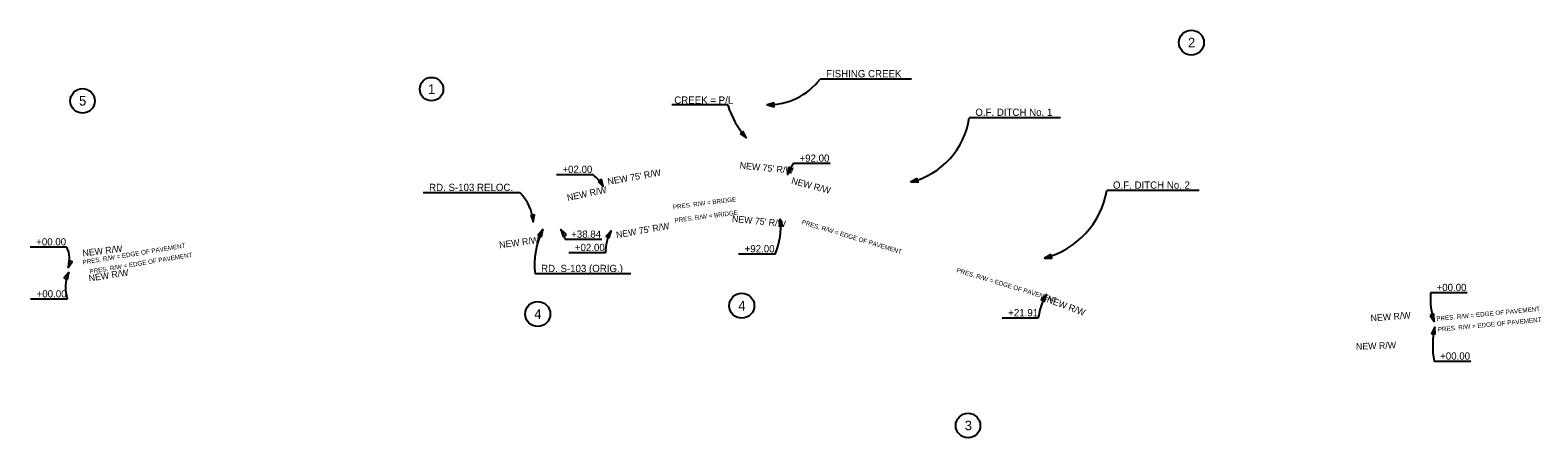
# Model space of a CAD drawing. Extents: x 1959715 to 1970746, y 1118442 to 1119852.
import ezdxf

# ---------------------------------------------------------------- set-up
doc = ezdxf.new("R2010")
doc.units = 0
for name, color, linetype in [('RD_EX_DV_TX_Prop', 7, 'Continuous'), ('RD_EX_RW_TX', 7, 'Continuous'), ('RD_PD_RW_TX', 7, 'Continuous'), ('RD_TX_RoadID', 7, 'Continuous')]:
    doc.layers.add(name, color=color, linetype=linetype)

msp = doc.modelspace()

# ---------------------------------------------------------------- linework, layer by layer
at = {"layer": 'RD_EX_DV_TX_Prop'}
msp.add_line((1968063.1, 1119604.2), (1967877.9, 1119604.2), dxfattribs=at)
msp.add_lwpolyline([(1968104.6, 1119508.1), (1968124.6, 1119494.8), (1968113.9, 1119516.3)], close=True, dxfattribs=at)
for centre, radius in [((1969598.8, 1119810.6), 41.4), ((1967082, 1119656.5), 38.9), ((1965926, 1119617.5), 40.6), ((1968109.5, 1118938.6), 41.6), ((1967433.8, 1118911), 41.6), ((1968858.9, 1118541.2), 40.7)]:
    msp.add_circle(centre, radius, dxfattribs=at)
msp.add_arc((1968348.3, 1119692.7), 298.6, 197.24, 221.4995, dxfattribs=at)
at = {"layer": 'RD_PD_RW_TX'}
for p, q in [((1967616.9, 1119372.6), (1967495.4, 1119372.6)), ((1968402.2, 1119409.7), (1968280.7, 1119409.7)), ((1965874, 1119132.3), (1965752.6, 1119132.3)), ((1967645.9, 1119157.7), (1967524.4, 1119157.7)), ((1967658.1, 1119113.7), (1967536.7, 1119113.7)), ((1968220.5, 1119109.5), (1968099.1, 1119109.5)), ((1970512.1, 1118981.1), (1970390.7, 1118981.1)), ((1965875.6, 1118959.9), (1965754.1, 1118959.9)), ((1969091.4, 1118897.3), (1968972, 1118897.3)), ((1970524.1, 1118753.8), (1970402.6, 1118753.8))]:
    msp.add_line(p, q, dxfattribs=at)
for points in [[(1968263.8, 1119397.6), (1968260.6, 1119373.8), (1968275.2, 1119392.9)], [(1967633.7, 1119350.8), (1967650.7, 1119333.9), (1967644.4, 1119357)], [(1968246, 1119203.4), (1968237, 1119225.7), (1968233.6, 1119201.9)], [(1967528.5, 1119174.9), (1967510.5, 1119190.7), (1967518.2, 1119168)], [(1967670.6, 1119163), (1967677, 1119186.2), (1967659.9, 1119169.3)], [(1965880.4, 1119088.6), (1965878.5, 1119064.7), (1965892.1, 1119084.4)], [(1965876.8, 1119025.3), (1965881.2, 1119048.9), (1965865.5, 1119030.7)], [(1969112.1, 1118952.5), (1969118.9, 1118975.5), (1969101.5, 1118959)], [(1970389.6, 1118906.2), (1970402.8, 1118886.1), (1970401.4, 1118910.1)], [(1970405.7, 1118843.7), (1970404.6, 1118867.7), (1970393.5, 1118846.4)]]:
    msp.add_lwpolyline(points, close=True, dxfattribs=at)
for centre, radius, start, end in [((1967533, 1119265.2), 136.2, 30.2443, 52.0147), ((1968422.4, 1119307), 175, 144.0429, 157.5334), ((1968010.3, 1119198.7), 228.4, 337.0173, 6.7984), ((1967431.6, 1119137.8), 95, 12.1375, 33.8624), ((1967795.6, 1119116.6), 137.5, 149.6145, 181.2295), ((1965797.9, 1119093.2), 85.5, 340.4703, 27.1445), ((1965988.6, 1118997.5), 119.1, 154.438, 198.4283), ((1969287.1, 1118872.5), 197.3, 148.5251, 172.7943), ((1970640.6, 1118964.7), 250.4, 176.2388, 198.2845), ((1970686, 1118805.9), 288.2, 167.6109, 190.4108)]:
    msp.add_arc(centre, radius, start, end, dxfattribs=at)
at = {"layer": 'RD_TX_RoadID'}
for p, q in [((1968672.2, 1119689.6), (1968368.7, 1119689.6)), ((1969165.6, 1119561.7), (1968863.1, 1119561.7)), ((1967375.5, 1119312.8), (1967053.9, 1119312.8)), ((1969623.9, 1119320.5), (1969319, 1119320.5)), ((1967741.6, 1119044.1), (1967424.8, 1119044.1))]:
    msp.add_line(p, q, dxfattribs=at)
for points in [[(1968217.2, 1119610.6), (1968194, 1119604.5), (1968217.1, 1119598.2)], [(1968690.3, 1119360.3), (1968669.2, 1119348.9), (1968693.2, 1119348.2)], [(1967410.7, 1119239), (1967418.6, 1119216.4), (1967423, 1119240)], [(1967445.8, 1119167.2), (1967450.9, 1119190.7), (1967434.8, 1119172.9)], [(1969132.9, 1119108.4), (1969112.1, 1119096.5), (1969136.1, 1119096.4)]]:
    msp.add_lwpolyline(points, close=True, dxfattribs=at)
for centre, radius, start, end in [((1968195.4, 1119823.7), 219.2, 269.6315, 322.2742), ((1968609.9, 1119597.6), 255.7, 283.4051, 351.9368), ((1967263, 1119204.7), 156, 4.285, 43.8577), ((1969041, 1119369.7), 282.2, 284.5784, 349.956), ((1967676.7, 1119075), 253.7, 152.8762, 186.9917)]:
    msp.add_arc(centre, radius, start, end, dxfattribs=at)

# ---------------------------------------------------------------- texts
at = {"layer": 'RD_EX_DV_TX_Prop'}
for s, height, p in [('2', 32, (1969587.4, 1119794.7)), ('1', 32, (1967070.3, 1119640.5)), ('5', 32, (1965914.6, 1119602.1)), ('CREEK = P/L', 24, (1967885.9, 1119608.2)), ('4', 32, (1967422.4, 1118895)), ('4', 32, (1968098.2, 1118922.6)), ('3', 32, (1968848.1, 1118525.5))]:
    msp.add_text(s, height=height, dxfattribs=at).set_placement(p)
at = {"layer": 'RD_EX_RW_TX'}
for s, rotation, p in [('PRES. R/W = BRIDGE', 7.2405, (1967882.3, 1119258.1)), ('PRES. R/W = BRIDGE', 7.2405, (1967887.9, 1119213.9)), ('PRES. R/W = EDGE OF PAVEMENT', 343.1604, (1968307, 1119209.3)), ('PRES. R/W = EDGE OF PAVEMENT', 9.4249, (1965927.7, 1119074.7)), ('PRES. R/W = EDGE OF PAVEMENT', 9.4249, (1965950.8, 1119043.9)), ('PRES. R/W = EDGE OF PAVEMENT', 343.1604, (1968819.4, 1119049.9)), ('PRES. R/W = EDGE OF PAVEMENT', 5.5247, (1970410.8, 1118887.8)), ('PRES. R/W = EDGE OF PAVEMENT', 5.5247, (1970415.6, 1118852.1))]:
    msp.add_text(s, height=15, rotation=rotation, dxfattribs=at).set_placement(p)
at = {"layer": 'RD_PD_RW_TX'}
for s, height, rotation, p in [("NEW 75' R/W", 21.818, 354.1794, (1968101.8, 1119393.3)), ("NEW 75' R/W", 21.818, 10.0887, (1967666.8, 1119339)), ('NEW R/W', 21.82, 345.1258, (1968272.1, 1119343.3)), ('NEW R/W', 21.82, 11.8653, (1967533.2, 1119285.6)), ("NEW 75' R/W", 21.818, 10.0887, (1967695.2, 1119162.1)), ("NEW 75' R/W", 21.818, 354.1794, (1968076.1, 1119216.9)), ('NEW R/W', 21.82, 7.8306, (1967307.4, 1119128.7)), ('NEW R/W', 21.82, 6.8189, (1965927.2, 1119101.8)), ('NEW R/W', 21.82, 8.7874, (1965948.1, 1119018.4)), ('NEW R/W', 21.82, 339.7241, (1969117.8, 1118950.7)), ('NEW R/W', 21.82, 4.3608, (1970193, 1118886.4)), ('NEW R/W', 21.82, 1.9718, (1970144, 1118792.5))]:
    msp.add_text(s, height=height, rotation=rotation, dxfattribs=at).set_placement(p)
for s, p in [('+92.00', (1968300.7, 1119415.7)), ('+02.00', (1967515.4, 1119378.6)), ('+00.00', (1965772.6, 1119138.3)), ('+38.84', (1967544.4, 1119163.7)), ('+02.00', (1967556.7, 1119119.7)), ('+92.00', (1968119.1, 1119115.5)), ('+00.00', (1965774.1, 1118965.9)), ('+00.00', (1970410.7, 1118987.1)), ('+21.91', (1968992, 1118903.3)), ('+00.00', (1970422.6, 1118759.8))]:
    msp.add_text(s, height=24, dxfattribs=at).set_placement(p)
at = {"layer": 'RD_TX_RoadID'}
for s, p in [('FISHING CREEK', (1968388.7, 1119695.6)), ('O.F. DITCH No. 1', (1968883.1, 1119567.7)), ('RD. S-103 RELOC.', (1967073.9, 1119318.8)), ('O.F. DITCH No. 2', (1969339, 1119326.5)), ('RD. S-103 (ORIG.)', (1967444.8, 1119050.1))]:
    msp.add_text(s, height=24, dxfattribs=at).set_placement(p)

doc.saveas('drawing.dxf')
